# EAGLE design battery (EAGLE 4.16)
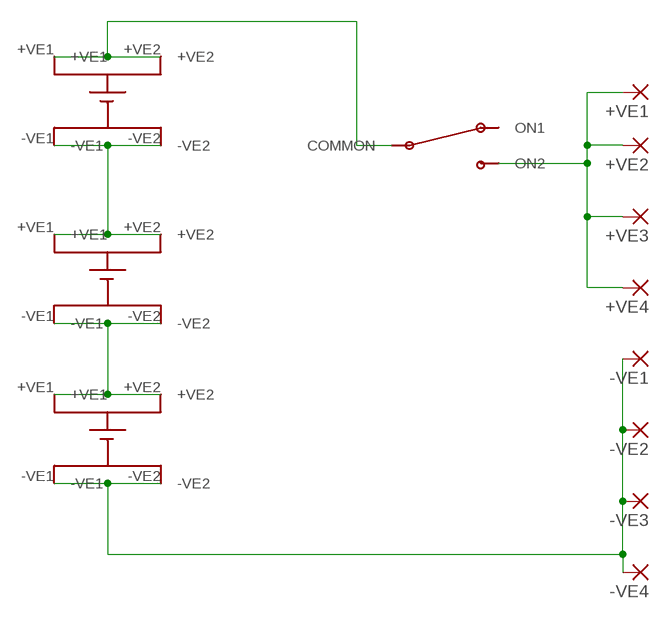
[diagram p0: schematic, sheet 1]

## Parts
+VE1  2,15/1,0  [2,15/1,0]
+VE2  2,15/1,0  [2,15/1,0]
+VE3  2,15/1,0  [2,15/1,0]
+VE4  2,15/1,0  [2,15/1,0]
-VE1  2,15/1,0  [2,15/1,0]
-VE2  2,15/1,0  [2,15/1,0]
-VE3  2,15/1,0  [2,15/1,0]
-VE4  2,15/1,0  [2,15/1,0]
U$1  AAABATT  [BATPAC]
U$2  AAABATT  [BATPAC]
U$3  AAABATT  [BATPAC]
U$4  ONOFFSWITCH  [SWITCHPAC]

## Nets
N$1: -VE1.1(P) -VE2.1(P) -VE3.1(P) -VE4.1(P) U$1.-VE1 U$1.-VE2
N$3: U$1.+VE1 U$1.+VE2 U$2.-VE1 U$2.-VE2
N$5: U$2.+VE1 U$2.+VE2 U$3.-VE1 U$3.-VE2
N$6: U$3.+VE1 U$3.+VE2 U$4.COMMON
N$7: +VE1.1(P) +VE2.1(P) +VE3.1(P) +VE4.1(P) U$4.ON2
Unconnected: U$4.ON1

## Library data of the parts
+VE1-+VE4 -VE1--VE4 = wirepad:2,15/1,0: THROUGH-HOLE PAD
U$1-U$3 = iain:AAABATT
U$4 = iain:ONOFFSWITCH

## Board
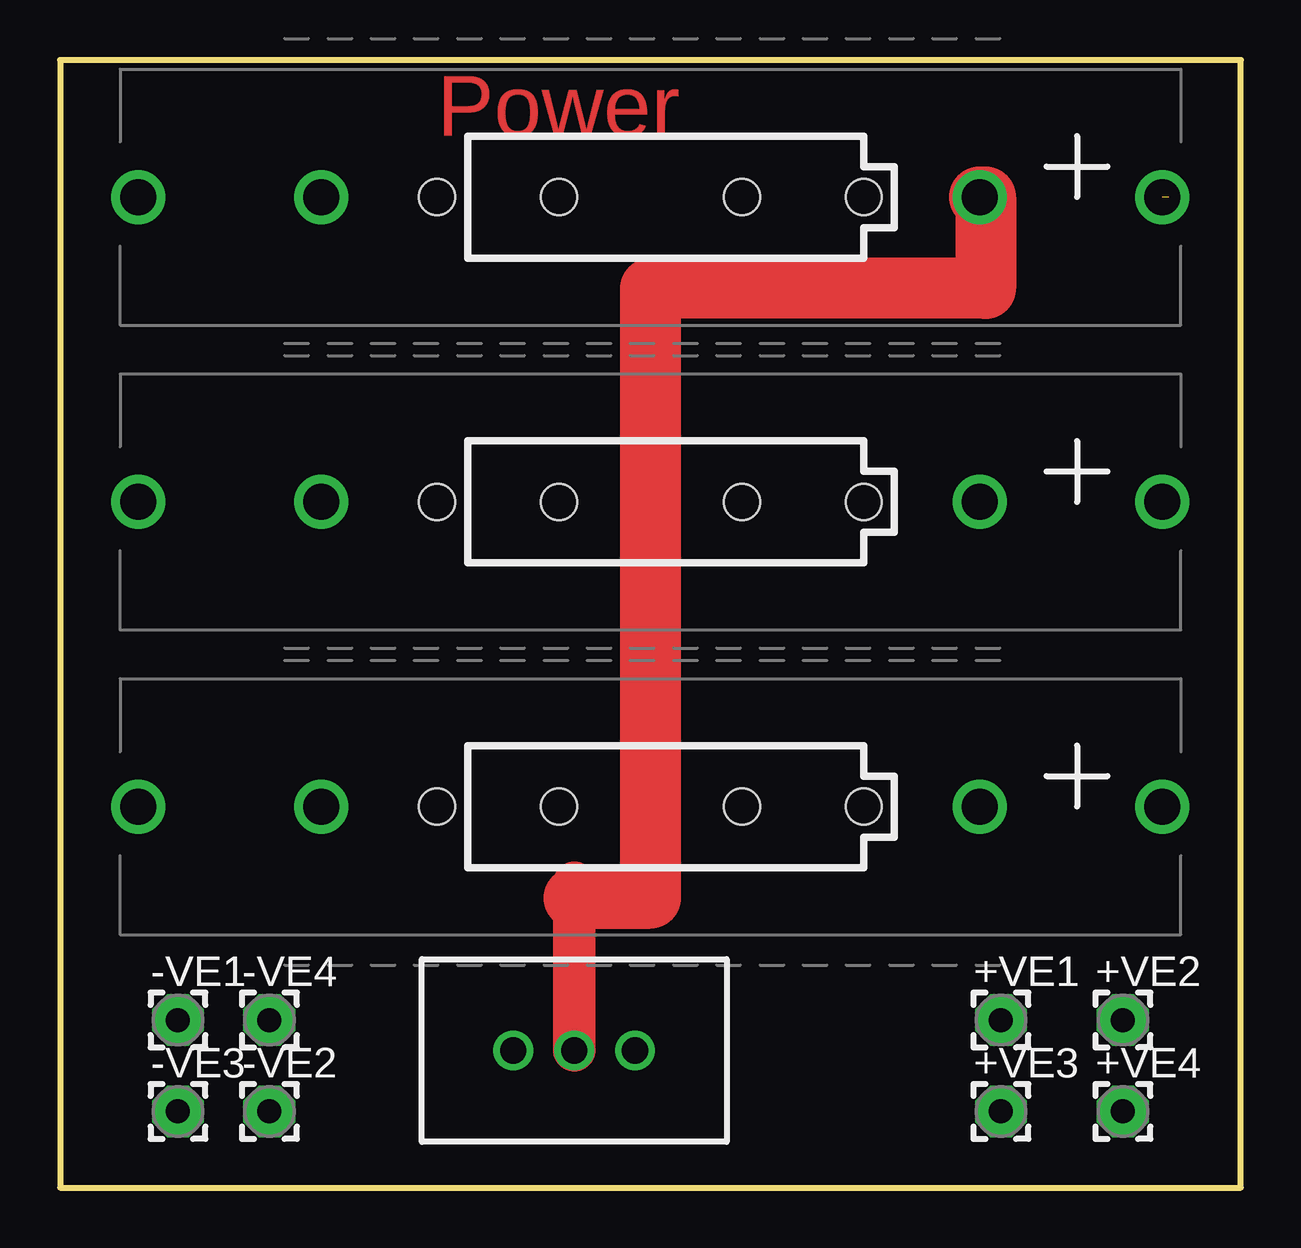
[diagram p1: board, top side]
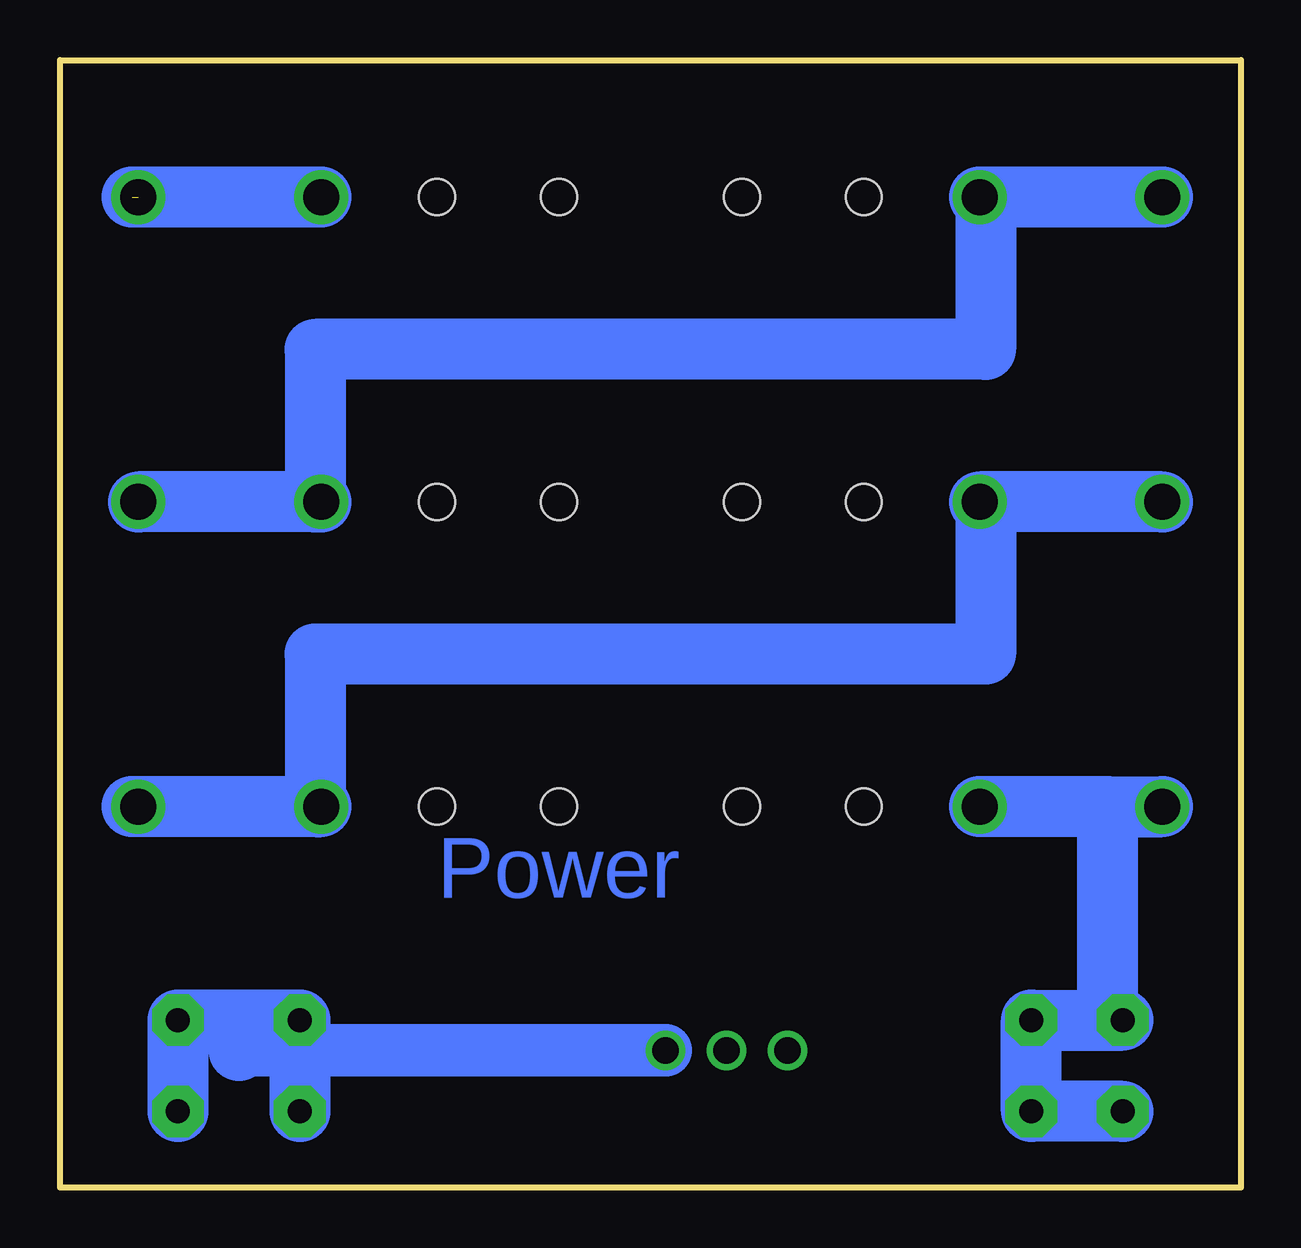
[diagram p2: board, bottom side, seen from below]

Size 49.2 x 46.98 mm. Coordinates in mm from the lower left corner, seen from the top.
Outline: 0,0 49.2,0 49.2,46.98 0,46.98 0,0
Copper layers (1*16): Top 0.035mm / dielectric 1.5mm / Bottom 0.035mm
Design rules "default": minimum track width 10mil, minimum drill 24mil, track to track 8mil, track to pad 8mil, pad to pad 8mil, via to via 8mil, smd to smd 8mil, copper to edge 40mil, drill to drill 8mil, minimum pad ring 10mil, minimum via ring 8mil, stop-mask expansion 4mil, vias tented up to drill 0mil, thermal gap 10mil
Holes 1.5 mm at 28.41,28.57 15.71,15.87 20.79,15.87 33.49,15.87 28.41,15.87 15.71,41.27 20.79,41.27 28.41,41.27 33.49,28.57 33.49,41.27 15.71,28.57 20.79,28.57

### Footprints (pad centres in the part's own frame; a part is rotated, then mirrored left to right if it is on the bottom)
2,15/1,0 = drill 1 pad 2.159 octagon: 1 0,0
BATPAC = drill 1.5 round: +VE1 13.716,0; +VE2 21.336,0; -VE1 -21.336,0; -VE2 -13.716,0
SWITCHPAC = drill 1.1 round: COMMON 0,0; ON1 -2.54,0; ON2 2.54,0

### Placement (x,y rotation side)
+VE1  39.21,6.98 0 top
+VE2  44.29,6.98 0 top
+VE3  39.21,3.17 0 top
+VE4  44.29,3.17 0 top
-VE1  4.92,6.98 0 top
-VE2  8.72,3.17 0 top
-VE3  4.92,3.17 0 top
-VE4  8.72,6.98 0 top
U$1  24.6,15.87 0 top
U$2  24.6,28.57 0 top
U$3  24.6,41.27 0 top
U$4  21.43,5.71 0 top

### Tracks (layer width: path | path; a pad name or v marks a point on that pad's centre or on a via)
N$1
  Bottom 2.54: 5.55,15.87 U$1.-VE1 | 5.55,15.87 U$1.-VE2 | -VE3.1 -VE2.1 -VE4.1 -VE1.1 5.55,6.98 5.55,15.87
N$3
  Bottom 2.54: U$2.-VE1 U$2.-VE2 10.63,28.57 10.63,22.22 38.57,22.22 38.57,15.87 | 46.19,15.87 U$1.+VE2 38.57,15.87 | 38.57,15.87 U$1.+VE1
N$5
  Bottom 2.54: U$3.-VE1 U$3.-VE2 10.63,41.27 10.63,34.92 38.57,34.92 38.57,28.57 | 38.57,28.57 U$2.+VE2 | 38.57,28.57 U$2.+VE1
N$6  (1 unrouted)
  Top 1.778: U$4.COMMON 21.43,12.06 21.43,12.7
  Top 2.54: 21.43,12.06 24.6,12.06 24.6,37.46 38.57,37.46 38.57,41.27 U$3.+VE1
  Bottom 2.54: U$3.+VE1 46.19,41.27
N$7
  Bottom 2.184: U$4.ON2 41.75,5.71
  Bottom 2.54: 41.75,5.71 +VE1.1 | +VE1.1 +VE2.1 +VE4.1 | +VE1.1 +VE3.1

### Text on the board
Top: Power
Bottom: Power
tNames: -VE1 | +VE1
